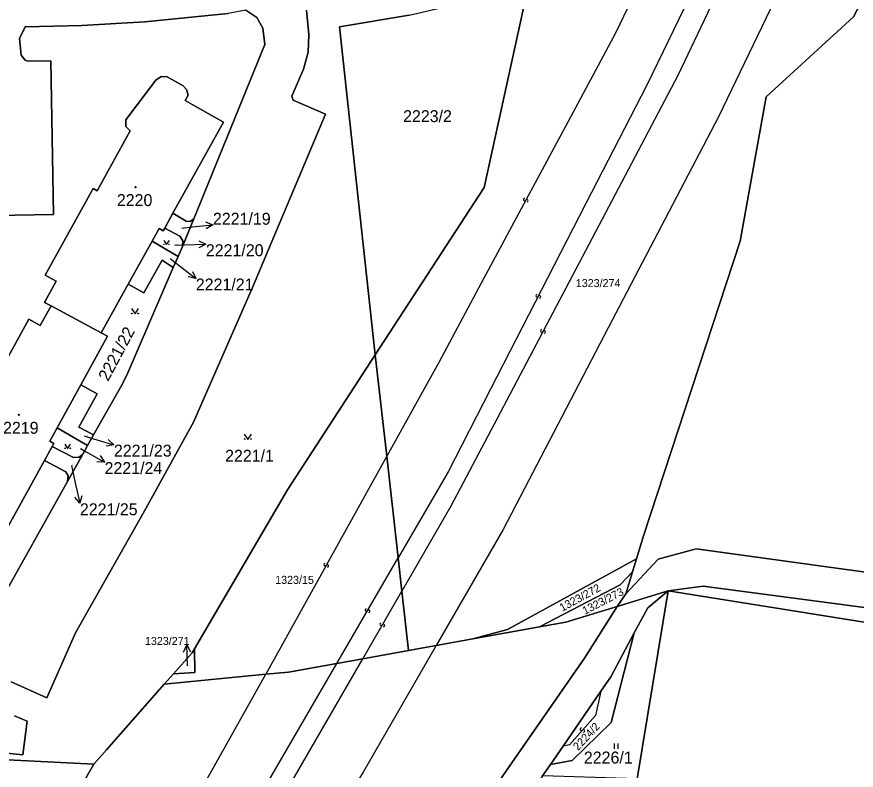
# Model space of a CAD drawing. Extents: x -596024 to -594475, y -1163820 to -1161957.
# Drawn here: x -595718.4 to -595598.9, y -1162998.7 to -1162891.5 of the extents above; entities that cross this region are included whole.
import ezdxf

# ---------------------------------------------------------------- set-up
doc = ezdxf.new("R2010")
doc.units = 0
for name, color, linetype in [('Level 1', 7, 'Continuous'), ('Level 13', 7, 'Continuous'), ('Level 3', 7, 'Continuous'), ('Level 4', 7, 'Continuous'), ('Level 5', 7, 'Continuous'), ('Level 57', 7, 'Continuous'), ('Level 60', 7, 'Continuous')]:
    doc.layers.add(name, color=color, linetype=linetype)

msp = doc.modelspace()

# ---------------------------------------------------------------- linework, layer by layer
at = {"layer": 'Level 1'}
for points in [[(-595630.19, -1162968.62), (-595629.19, -1162965.35), (-595615.44, -1162923.38), (-595611.72, -1162902.85), (-595599.31, -1162891.47), (-595588.22, -1162870.34)], [(-595667.38, -1162939.58), (-595672.49, -1162892.86), (-595662.54, -1162891.24), (-595655.79, -1162889.65), (-595645.71, -1162887.95)], [(-595645.71, -1162887.95), (-595645.96, -1162888.65), (-595651.89, -1162915.77), (-595667.38, -1162939.58)], [(-595693.22, -1162920.24), (-595683.12, -1162895.39), (-595683.38, -1162893.05), (-595684.22, -1162891.57), (-595685.82, -1162890.52), (-595688.3, -1162890.99), (-595700.2, -1162892.18), (-595709.16, -1162892.71), (-595717.23, -1162892.88), (-595718.04, -1162894.54), (-595717.8, -1162896.93), (-595717.22, -1162897.62), (-595716.82, -1162897.78), (-595713.57, -1162897.71), (-595713.19, -1162919.59), (-595726.95, -1162919.86), (-595727.33, -1162903.91), (-595724.32, -1162903.81), (-595723.24, -1162903.33), (-595722.76, -1162902.31), (-595722.85, -1162899.32)], [(-595677.17, -1162890.52), (-595676.82, -1162893.99), (-595676.91, -1162896.47), (-595677.6, -1162898.92), (-595679.26, -1162902.77), (-595679.06, -1162903.34), (-595674.47, -1162905.32), (-595684.86, -1162930.01), (-595693.24, -1162949.18), (-595700.3, -1162961.9), (-595710.04, -1162979.15), (-595714.14, -1162988.41), (-595719.22, -1162986.15)], [(-595696.19, -1162919.43), (-595688.99, -1162906.45), (-595694.45, -1162903.39), (-595694.01, -1162902.63), (-595694.23, -1162901.79), (-595694.71, -1162901.26), (-595697.01, -1162899.98), (-595697.86, -1162899.95), (-595698.6, -1162900.47), (-595702.88, -1162906.13), (-595702.91, -1162907.06), (-595702.25, -1162907.7), (-595706.97, -1162916.22), (-595707.56, -1162915.9), (-595714.36, -1162928.22), (-595712.81, -1162929.09), (-595714.49, -1162932.12), (-595713.54, -1162932.62)], [(-595696.19, -1162919.43), (-595697.35, -1162921.53)], [(-595693.22, -1162920.24), (-595693.73, -1162920.62), (-595694.3, -1162920.55), (-595696.19, -1162919.43)], [(-595694.82, -1162924.14), (-595693.22, -1162920.24)], [(-595697.35, -1162921.53), (-595697.57, -1162921.93), (-595698.16, -1162921.6), (-595699.15, -1162923.39)], [(-595697.35, -1162921.53), (-595695.22, -1162922.69), (-595694.76, -1162923.34), (-595694.82, -1162924.14)], [(-595699.15, -1162923.39), (-595702.54, -1162929.51)], [(-595699.15, -1162923.39), (-595695.45, -1162925.59)], [(-595695.45, -1162925.59), (-595694.82, -1162924.14)], [(-595702.54, -1162929.51), (-595700.31, -1162930.75), (-595697.74, -1162926.11), (-595696.14, -1162927.15)], [(-595696.14, -1162927.15), (-595695.45, -1162925.59)], [(-595707.48, -1162951), (-595703.61, -1162944.16), (-595702.77, -1162942.46), (-595696.14, -1162927.15)], [(-595702.54, -1162929.51), (-595706.38, -1162936.44)], [(-595714.48, -1162954.64), (-595721.66, -1162967.63), (-595727.51, -1162964.42), (-595727.84, -1162965.02), (-595728.39, -1162965.52), (-595729.16, -1162965.5), (-595731.52, -1162964.15), (-595732.1, -1162963.32), (-595732.02, -1162962.36), (-595729.25, -1162956.09), (-595728.72, -1162955.58), (-595727.97, -1162955.63), (-595727.68, -1162955.8), (-595722.91, -1162947.21), (-595723.53, -1162946.88), (-595716.68, -1162934.52), (-595715.1, -1162935.42), (-595713.54, -1162932.62)], [(-595713.54, -1162932.62), (-595706.38, -1162936.44)], [(-595709.29, -1162943.85), (-595705.48, -1162936.94), (-595706.38, -1162936.44)], [(-595667.38, -1162939.58), (-595679.87, -1162958.79), (-595693.12, -1162981.45)], [(-595667.38, -1162939.58), (-595665.75, -1162954.03)], [(-595709.29, -1162943.85), (-595712.68, -1162949.98)], [(-595707.48, -1162951), (-595709.6, -1162949.89), (-595706.97, -1162945.13), (-595709.29, -1162943.85)], [(-595712.68, -1162949.98), (-595713.72, -1162951.86), (-595713.12, -1162952.19), (-595713.36, -1162952.62)], [(-595708.33, -1162952.49), (-595712.68, -1162949.98)], [(-595708.33, -1162952.49), (-595707.48, -1162951)], [(-595709.02, -1162953.74), (-595708.33, -1162952.49)], [(-595713.36, -1162952.62), (-595714.48, -1162954.64)], [(-595713.36, -1162952.62), (-595710.35, -1162954.19), (-595709.54, -1162954.17), (-595709.02, -1162953.74)], [(-595711.21, -1162957.6), (-595711.09, -1162956.83), (-595711.41, -1162956.25), (-595714.48, -1162954.64)], [(-595709.02, -1162953.74), (-595711.21, -1162957.6)], [(-595665.75, -1162954.03), (-595664.12, -1162968.5)], [(-595745.94, -1162977.39), (-595743.24, -1162978.4), (-595735.08, -1162983.24), (-595732.84, -1162984.27), (-595731.36, -1162984.28), (-595729.42, -1162983.44), (-595726.53, -1162980.93), (-595727.15, -1162979.82), (-595728.41, -1162978.62), (-595730.66, -1162982.6), (-595742.82, -1162975.76), (-595740.35, -1162971.64), (-595737.88, -1162967.26), (-595729.97, -1162971.67), (-595727.71, -1162967.77), (-595723.54, -1162970.18), (-595725.76, -1162974.06), (-595724.16, -1162974.93), (-595722.52, -1162975.26), (-595721.06, -1162975.18), (-595711.21, -1162957.6)], [(-595631.72, -1162973.61), (-595627.1, -1162968.66), (-595621.68, -1162967.22), (-595580.37, -1162972.91), (-595548.72, -1162976.84), (-595533.58, -1162977.77), (-595526.44, -1162978.13), (-595523.36, -1162976.45), (-595521.48, -1162971.75)], [(-595664.12, -1162968.5), (-595663.59, -1162973.22)], [(-595653.47, -1162980.02), (-595648.57, -1162978.69), (-595630.19, -1162968.62)], [(-595630.76, -1162970.47), (-595630.19, -1162968.62)], [(-595644.02, -1162978.31), (-595632.51, -1162972.36), (-595630.76, -1162970.47)], [(-595631.72, -1162973.61), (-595630.76, -1162970.47)], [(-595625.67, -1162973.19), (-595620.68, -1162972.51), (-595581.97, -1162977.67), (-595549.49, -1162981.93), (-595533.77, -1162984.14), (-595525.67, -1162985.49), (-595519.93, -1162988.52)], [(-595663.59, -1162973.22), (-595662.64, -1162981.68)], [(-595625.67, -1162973.19), (-595632.94, -1162975.42)], [(-595632.94, -1162975.42), (-595631.72, -1162973.61)], [(-595630.51, -1162979.19), (-595628.58, -1162975.6), (-595625.67, -1162973.19)], [(-595625.67, -1162973.19), (-595630.09, -1162999.96)], [(-595519.69, -1162990.12), (-595625.67, -1162973.19)], [(-595703.87, -1163071.37), (-595698.09, -1163065.01), (-595678.51, -1163041.57), (-595661.53, -1163017.48), (-595648.68, -1162998.76), (-595637.58, -1162982.79), (-595632.94, -1162975.42)], [(-595632.94, -1162975.42), (-595640.24, -1162977.63), (-595644.02, -1162978.31)], [(-595644.02, -1162978.31), (-595653.47, -1162980.02)], [(-595630.51, -1162979.19), (-595633.77, -1162991.96), (-595639.33, -1162997.36), (-595642.45, -1162997.93)], [(-595635.27, -1162987.48), (-595633.85, -1162985.42), (-595630.51, -1162979.19)], [(-595658.71, -1162980.97), (-595662.64, -1162981.68)], [(-595653.47, -1162980.02), (-595658.71, -1162980.97)], [(-595696.12, -1162985), (-595693.45, -1162982.01), (-595693.12, -1162981.45)], [(-595696.12, -1162985), (-595693.09, -1162984.81), (-595693.12, -1162981.45)], [(-595662.64, -1162981.68), (-595669.16, -1162982.86)], [(-595682.97, -1162985.08), (-595679.73, -1162984.77), (-595672.85, -1162983.53)], [(-595669.16, -1162982.86), (-595672.85, -1162983.53)], [(-595696.12, -1162985), (-595697.43, -1162986.48)], [(-595682.97, -1162985.08), (-595697.43, -1162986.48)], [(-595697.43, -1162986.48), (-595703.26, -1162993.12), (-595705.64, -1162995.83), (-595707.44, -1162997.87)], [(-595640.64, -1162995.3), (-595635.27, -1162987.48)], [(-595718.76, -1162990.98), (-595716.93, -1162991.75), (-595717.54, -1162996.55), (-595723.49, -1162995.94)], [(-595642.45, -1162997.93), (-595640.64, -1162995.3)], [(-595746.22, -1162995.91), (-595707.44, -1162997.87)], [(-595707.44, -1162997.87), (-595718.62, -1163017.24)], [(-595643.56, -1162999.54), (-595642.45, -1162997.93)]]:
    msp.add_lwpolyline(points, dxfattribs=at)
at = {"layer": 'Level 13'}
for centre, start, end in [((-595646.11, -1162917.47), 98.9414, 331.5314), ((-595645.79, -1162917.65), 279.1558, 151.2538), ((-595644.33, -1162931.18), 99.9549, 332.5449), ((-595644.01, -1162931.35), 280.1694, 152.2674), ((-595643.66, -1162936.16), 99.3651, 331.9551), ((-595643.34, -1162936.34), 279.5796, 151.6776), ((-595674.52, -1162969.47), 98.146, 330.736), ((-595674.2, -1162969.65), 278.3605, 150.4584), ((-595668.64, -1162975.93), 97.2231, 329.3211), ((-595668.32, -1162976.11), 277.0086, 149.5986), ((-595666.54, -1162977.95), 97.3534, 329.4514), ((-595666.22, -1162978.13), 277.1389, 149.7289), ((-595638.02, -1162992.9), 85.4308, 318.0208), ((-595637.74, -1162993.14), 265.6453, 137.7433)]:
    msp.add_arc(centre, 0.184, start, end, dxfattribs=at)
at = {"layer": 'Level 3'}
for points in [[(-595603.73, -1162874.99), (-595618.53, -1162905.68), (-595634.2, -1162935.72), (-595649.19, -1162964.46), (-595652.89, -1162970.88), (-595658.71, -1162980.97)], [(-595614.02, -1162878.11), (-595624.29, -1162899.81), (-595636.5, -1162922.96), (-595650.51, -1162949.54), (-595656.61, -1162961.12), (-595663.59, -1162973.22)], [(-595618.13, -1162879.3), (-595628.71, -1162901.18), (-595637.38, -1162918.05), (-595650.96, -1162944.47), (-595657.02, -1162956.27), (-595664.12, -1162968.5)], [(-595627.61, -1162882.17), (-595633.14, -1162893.7), (-595639.6, -1162905.74), (-595652.29, -1162929.39), (-595658.34, -1162940.67), (-595665.75, -1162954.03)], [(-595665.75, -1162954.03), (-595682.97, -1162985.08)], [(-595672.85, -1162983.53), (-595664.12, -1162968.5)], [(-595669.16, -1162982.86), (-595663.59, -1162973.22)], [(-595658.71, -1162980.97), (-595669.11, -1162999.02), (-595691.04, -1163034.53), (-595716.06, -1163070.56)], [(-595728.81, -1163069.72), (-595688.36, -1163010.24), (-595672.85, -1162983.53)], [(-595725.06, -1163069.97), (-595689.64, -1163018.35), (-595669.16, -1162982.86)], [(-595738.74, -1163069.07), (-595718.73, -1163041.4), (-595695.75, -1163007.92), (-595682.97, -1162985.08)], [(-595635.27, -1162987.48), (-595636.03, -1162990.94), (-595639.74, -1162995.1), (-595640.64, -1162995.3)]]:
    msp.add_lwpolyline(points, dxfattribs=at)
at = {"layer": 'Level 5'}
for p, q in [((-595633.3, -1162995.7), (-595633.3, -1162994.94)), ((-595632.8, -1162995.7), (-595632.8, -1162994.94))]:
    msp.add_line(p, q, dxfattribs=at)
for points in [[(-595697.49, -1162923.29), (-595697.09, -1162923.89), (-595696.69, -1162923.29)], [(-595702.08, -1162932.99), (-595701.58, -1162933.74), (-595701.08, -1162932.99)], [(-595686.02, -1162950.88), (-595685.52, -1162951.63), (-595685.02, -1162950.88)], [(-595711.58, -1162952.33), (-595711.18, -1162952.93), (-595710.78, -1162952.33)]]:
    msp.add_lwpolyline(points, dxfattribs=at)
for centre, radius in [((-595701.52, -1162915.7), 0.09), ((-595701.52, -1162915.7), 0.0521), ((-595697.45, -1162923.85), 0.04), ((-595696.73, -1162923.85), 0.04), ((-595702.03, -1162933.69), 0.05), ((-595701.13, -1162933.69), 0.05), ((-595718.12, -1162948.13), 0.09), ((-595718.12, -1162948.13), 0.0521), ((-595685.97, -1162951.58), 0.05), ((-595685.07, -1162951.58), 0.05), ((-595711.54, -1162952.89), 0.04), ((-595710.82, -1162952.89), 0.04)]:
    msp.add_circle(centre, radius, dxfattribs=at)
at = {"layer": 'Level 57'}
for p, q in [((-595694.94, -1162921.53), (-595693.47, -1162921.38)), ((-595693.47, -1162921.38), (-595690.49, -1162921.06)), ((-595695.93, -1162923.97), (-595694.5, -1162923.93)), ((-595694.5, -1162923.93), (-595691.5, -1162923.84)), ((-595696.55, -1162925.9), (-595695.3, -1162926.88)), ((-595695.3, -1162926.88), (-595692.93, -1162928.72)), ((-595708.83, -1162951.14), (-595707.47, -1162951.54)), ((-595707.47, -1162951.54), (-595704.59, -1162952.38)), ((-595709.34, -1162952.94), (-595708.54, -1162953.39)), ((-595708.54, -1162953.39), (-595705.92, -1162954.86)), ((-595710.62, -1162955.33), (-595710.08, -1162957.8)), ((-595710.08, -1162957.8), (-595709.43, -1162960.73)), ((-595694.1, -1162983.89), (-595694.19, -1162980.9))]:
    msp.add_line(p, q, dxfattribs=at)
for points in [[(-595691.54, -1162920.67), (-595690.49, -1162921.06), (-595691.43, -1162921.66)], [(-595692.52, -1162923.37), (-595691.5, -1162923.84), (-595692.48, -1162924.37)], [(-595693.41, -1162927.71), (-595692.93, -1162928.72), (-595694.03, -1162928.5)], [(-595705.41, -1162951.62), (-595704.59, -1162952.38), (-595705.69, -1162952.58)], [(-595706.55, -1162953.93), (-595705.92, -1162954.86), (-595707.04, -1162954.81)], [(-595709.16, -1162959.65), (-595709.43, -1162960.73), (-595710.13, -1162959.86)], [(-595694.66, -1162981.91), (-595694.19, -1162980.9), (-595693.66, -1162981.88)]]:
    msp.add_lwpolyline(points, dxfattribs=at)
at = {"layer": 'Level 60'}
for points in [[(-595533.58, -1162977.77), (-595548.72, -1162976.84), (-595580.37, -1162972.91), (-595621.68, -1162967.22), (-595627.1, -1162968.66), (-595631.72, -1162973.61), (-595630.76, -1162970.47), (-595630.19, -1162968.62), (-595629.19, -1162965.35), (-595615.44, -1162923.38), (-595611.72, -1162902.85), (-595599.31, -1162891.47), (-595588.22, -1162870.34), (-595577.24, -1162866.72), (-595550.23, -1162857.95), (-595540.49, -1162858.64), (-595532.01, -1162864.98), (-595527.95, -1162892.49), (-595526.75, -1162917.62), (-595523.56, -1162952.96), (-595522.19, -1162968.12), (-595521.48, -1162971.75), (-595523.36, -1162976.45), (-595526.44, -1162978.13)], [(-595645.96, -1162888.65), (-595651.89, -1162915.77), (-595667.38, -1162939.58), (-595672.49, -1162892.86), (-595662.54, -1162891.24), (-595655.79, -1162889.65), (-595645.71, -1162887.95)], [(-595706.38, -1162936.44), (-595713.54, -1162932.62), (-595714.49, -1162932.12), (-595712.81, -1162929.09), (-595714.36, -1162928.22), (-595707.56, -1162915.9), (-595706.97, -1162916.22), (-595702.25, -1162907.7), (-595702.91, -1162907.06), (-595702.88, -1162906.13), (-595698.6, -1162900.47), (-595697.86, -1162899.95), (-595697.01, -1162899.98), (-595694.71, -1162901.26), (-595694.23, -1162901.79), (-595694.01, -1162902.63), (-595694.45, -1162903.39), (-595688.99, -1162906.45), (-595696.19, -1162919.43), (-595697.35, -1162921.53), (-595697.57, -1162921.93), (-595698.16, -1162921.6), (-595699.15, -1162923.39), (-595702.54, -1162929.51)], [(-595693.22, -1162920.24), (-595694.82, -1162924.14), (-595694.76, -1162923.34), (-595695.22, -1162922.69), (-595697.35, -1162921.53), (-595696.19, -1162919.43), (-595694.3, -1162920.55), (-595693.73, -1162920.62)], [(-595694.82, -1162924.14), (-595695.45, -1162925.59), (-595699.15, -1162923.39), (-595698.16, -1162921.6), (-595697.57, -1162921.93), (-595697.35, -1162921.53), (-595695.22, -1162922.69), (-595694.76, -1162923.34)], [(-595695.45, -1162925.59), (-595696.14, -1162927.15), (-595697.74, -1162926.11), (-595700.31, -1162930.75), (-595702.54, -1162929.51), (-595699.15, -1162923.39)], [(-595696.14, -1162927.15), (-595702.77, -1162942.46), (-595703.61, -1162944.16), (-595707.48, -1162951), (-595709.6, -1162949.89), (-595706.97, -1162945.13), (-595709.29, -1162943.85), (-595705.48, -1162936.94), (-595706.38, -1162936.44), (-595702.54, -1162929.51), (-595700.31, -1162930.75), (-595697.74, -1162926.11)], [(-595679.87, -1162958.79), (-595667.38, -1162939.58), (-595665.75, -1162954.03), (-595664.12, -1162968.5), (-595663.59, -1162973.22), (-595662.64, -1162981.68), (-595669.16, -1162982.86), (-595672.85, -1162983.53), (-595679.73, -1162984.77), (-595682.97, -1162985.08), (-595697.43, -1162986.48), (-595696.12, -1162985), (-595693.09, -1162984.81), (-595693.12, -1162981.45)], [(-595707.48, -1162951), (-595708.33, -1162952.49), (-595712.68, -1162949.98), (-595709.29, -1162943.85), (-595706.97, -1162945.13), (-595709.6, -1162949.89)], [(-595708.33, -1162952.49), (-595709.02, -1162953.74), (-595709.54, -1162954.17), (-595710.35, -1162954.19), (-595713.36, -1162952.62), (-595713.12, -1162952.19), (-595713.72, -1162951.86), (-595712.68, -1162949.98)], [(-595709.02, -1162953.74), (-595711.21, -1162957.6), (-595711.09, -1162956.83), (-595711.41, -1162956.25), (-595714.48, -1162954.64), (-595713.36, -1162952.62), (-595710.35, -1162954.19), (-595709.54, -1162954.17)], [(-595632.94, -1162975.42), (-595631.72, -1162973.61), (-595627.1, -1162968.66), (-595621.68, -1162967.22), (-595580.37, -1162972.91), (-595548.72, -1162976.84), (-595533.58, -1162977.77), (-595526.44, -1162978.13), (-595523.36, -1162976.45), (-595521.48, -1162971.75), (-595520.8, -1162972.23), (-595515.96, -1162992.22), (-595519.93, -1162988.52), (-595525.67, -1162985.49), (-595533.77, -1162984.14), (-595549.49, -1162981.93), (-595581.97, -1162977.67), (-595620.68, -1162972.51), (-595625.67, -1162973.19)], [(-595644.02, -1162978.31), (-595653.47, -1162980.02), (-595648.57, -1162978.69), (-595630.19, -1162968.62), (-595630.76, -1162970.47), (-595632.51, -1162972.36)], [(-595631.72, -1162973.61), (-595632.94, -1162975.42), (-595640.24, -1162977.63), (-595644.02, -1162978.31), (-595632.51, -1162972.36), (-595630.76, -1162970.47)], [(-595549.49, -1162981.93), (-595533.77, -1162984.14), (-595525.67, -1162985.49), (-595519.93, -1162988.52), (-595519.69, -1162990.12), (-595625.67, -1162973.19), (-595620.68, -1162972.51), (-595581.97, -1162977.67)], [(-595642.03, -1162999.6), (-595643.56, -1162999.54), (-595642.45, -1162997.93), (-595639.33, -1162997.36), (-595633.77, -1162991.96), (-595630.51, -1162979.19), (-595628.58, -1162975.6), (-595625.67, -1162973.19), (-595630.09, -1162999.96)], [(-595636.96, -1163041.67), (-595636.94, -1163041.47), (-595633.71, -1163021.93), (-595630.09, -1162999.96), (-595625.67, -1162973.19), (-595519.69, -1162990.12), (-595520.77, -1162996.86), (-595530.65, -1163058.63), (-595530.95, -1163058.58), (-595542.17, -1163056.79), (-595553.89, -1163054.92), (-595577.37, -1163051.18), (-595614.28, -1163045.29)], [(-595642.45, -1162997.93), (-595640.64, -1162995.3), (-595635.27, -1162987.48), (-595633.85, -1162985.42), (-595630.51, -1162979.19), (-595633.77, -1162991.96), (-595639.33, -1162997.36)], [(-595696.12, -1162985), (-595693.45, -1162982.01), (-595693.12, -1162981.45), (-595693.09, -1162984.81)], [(-595746.55, -1163016.16), (-595746.22, -1162995.91), (-595707.44, -1162997.87), (-595718.62, -1163017.24)]]:
    msp.add_lwpolyline(points, close=True, dxfattribs=at)
for points in [[(-595588.22, -1162870.34), (-595599.31, -1162891.47), (-595611.72, -1162902.85), (-595615.44, -1162923.38), (-595629.19, -1162965.35), (-595630.19, -1162968.62), (-595648.57, -1162978.69), (-595653.47, -1162980.02), (-595658.71, -1162980.97), (-595662.64, -1162981.68), (-595663.59, -1162973.22), (-595664.12, -1162968.5), (-595665.75, -1162954.03), (-595667.38, -1162939.58), (-595651.89, -1162915.77), (-595645.96, -1162888.65)], [(-595662.54, -1162891.24), (-595672.49, -1162892.86), (-595667.38, -1162939.58), (-595679.87, -1162958.79), (-595693.12, -1162981.45), (-595693.45, -1162982.01), (-595696.12, -1162985), (-595697.43, -1162986.48), (-595703.26, -1162993.12), (-595705.64, -1162995.83), (-595707.44, -1162997.87), (-595746.22, -1162995.91)], [(-595688.3, -1162890.99), (-595700.2, -1162892.18), (-595709.16, -1162892.71), (-595717.23, -1162892.88), (-595718.04, -1162894.54), (-595717.8, -1162896.93), (-595717.22, -1162897.62), (-595716.82, -1162897.78), (-595713.57, -1162897.71), (-595713.19, -1162919.59), (-595726.95, -1162919.86)], [(-595685.82, -1162890.52), (-595684.22, -1162891.57), (-595683.38, -1162893.05), (-595683.12, -1162895.39), (-595693.22, -1162920.24), (-595693.73, -1162920.62), (-595694.3, -1162920.55), (-595696.19, -1162919.43), (-595688.99, -1162906.45), (-595694.45, -1162903.39), (-595694.01, -1162902.63), (-595694.23, -1162901.79), (-595694.71, -1162901.26), (-595697.01, -1162899.98), (-595697.86, -1162899.95), (-595698.6, -1162900.47), (-595702.88, -1162906.13), (-595702.91, -1162907.06), (-595702.25, -1162907.7), (-595706.97, -1162916.22), (-595707.56, -1162915.9), (-595714.36, -1162928.22), (-595712.81, -1162929.09), (-595714.49, -1162932.12), (-595713.54, -1162932.62), (-595715.1, -1162935.42), (-595716.68, -1162934.52), (-595723.53, -1162946.88)], [(-595721.06, -1162975.18), (-595711.21, -1162957.6), (-595709.02, -1162953.74), (-595708.33, -1162952.49), (-595707.48, -1162951), (-595703.61, -1162944.16), (-595702.77, -1162942.46), (-595696.14, -1162927.15), (-595695.45, -1162925.59), (-595694.82, -1162924.14), (-595693.22, -1162920.24), (-595683.12, -1162895.39), (-595683.38, -1162893.05), (-595684.22, -1162891.57), (-595685.82, -1162890.52)], [(-595719.22, -1162986.15), (-595714.14, -1162988.41), (-595710.04, -1162979.15), (-595700.3, -1162961.9), (-595693.24, -1162949.18), (-595684.86, -1162930.01), (-595674.47, -1162905.32), (-595679.06, -1162903.34), (-595679.26, -1162902.77), (-595677.6, -1162898.92), (-595676.91, -1162896.47), (-595676.82, -1162893.99), (-595677.17, -1162890.52)], [(-595677.17, -1162890.52), (-595676.82, -1162893.99), (-595676.91, -1162896.47), (-595677.6, -1162898.92), (-595679.26, -1162902.77), (-595679.06, -1162903.34), (-595674.47, -1162905.32), (-595684.86, -1162930.01), (-595693.24, -1162949.18), (-595700.3, -1162961.9), (-595710.04, -1162979.15), (-595714.14, -1162988.41), (-595719.22, -1162986.15)], [(-595717.8, -1162896.93), (-595718.04, -1162894.54), (-595717.23, -1162892.88), (-595709.16, -1162892.71), (-595700.2, -1162892.18), (-595688.3, -1162890.99)], [(-595726.95, -1162919.86), (-595713.19, -1162919.59), (-595713.57, -1162897.71), (-595716.82, -1162897.78), (-595717.22, -1162897.62), (-595717.8, -1162896.93)], [(-595723.53, -1162946.88), (-595716.68, -1162934.52), (-595715.1, -1162935.42), (-595713.54, -1162932.62), (-595706.38, -1162936.44), (-595705.48, -1162936.94), (-595709.29, -1162943.85), (-595712.68, -1162949.98), (-595713.72, -1162951.86), (-595713.12, -1162952.19), (-595713.36, -1162952.62), (-595714.48, -1162954.64), (-595721.66, -1162967.63)], [(-595721.66, -1162967.63), (-595714.48, -1162954.64), (-595711.41, -1162956.25), (-595711.09, -1162956.83), (-595711.21, -1162957.6), (-595721.06, -1162975.18)], [(-595698.09, -1163065.01), (-595678.51, -1163041.57), (-595661.53, -1163017.48), (-595648.68, -1162998.76), (-595637.58, -1162982.79), (-595632.94, -1162975.42), (-595625.67, -1162973.19), (-595628.58, -1162975.6), (-595630.51, -1162979.19), (-595633.85, -1162985.42), (-595635.27, -1162987.48), (-595640.64, -1162995.3), (-595642.45, -1162997.93), (-595643.56, -1162999.54), (-595655.99, -1163017.63), (-595657.25, -1163019.45), (-595657.45, -1163019.75), (-595658.64, -1163021.44), (-595666.72, -1163032.91), (-595674.26, -1163043.61), (-595674.71, -1163044.25), (-595689.34, -1163060.83), (-595690.94, -1163062.64), (-595695.02, -1163067.26)], [(-595718.62, -1163017.24), (-595707.44, -1162997.87), (-595705.64, -1162995.83), (-595703.26, -1162993.12), (-595697.43, -1162986.48), (-595682.97, -1162985.08), (-595679.73, -1162984.77), (-595672.85, -1162983.53), (-595669.16, -1162982.86), (-595662.64, -1162981.68), (-595658.71, -1162980.97), (-595653.47, -1162980.02), (-595644.02, -1162978.31), (-595640.24, -1162977.63), (-595632.94, -1162975.42), (-595637.58, -1162982.79), (-595648.68, -1162998.76), (-595661.53, -1163017.48), (-595678.51, -1163041.57), (-595698.09, -1163065.01)], [(-595723.49, -1162995.94), (-595717.54, -1162996.55), (-595716.93, -1162991.75), (-595718.76, -1162990.98)], [(-595718.76, -1162990.98), (-595716.93, -1162991.75), (-595717.54, -1162996.55), (-595723.49, -1162995.94)]]:
    msp.add_lwpolyline(points, dxfattribs=at)

# ---------------------------------------------------------------- texts
at = {"layer": 'Level 4'}
for s, height, p in [('2223/2', 1.7, (-595663.42, -1162906.45)), ('2220', 1.7, (-595704.17, -1162918.4)), ('2221/19', 0.1, (-595694.94, -1162921.53)), ('2221/20', 0.1, (-595695.93, -1162923.97)), ('2221/21', 0.1, (-595696.55, -1162925.9)), ('1323/274', 1.14, (-595638.83, -1162929.94)), ('2219', 1.7, (-595720.37, -1162950.83)), ('2221/23', 0.1, (-595708.83, -1162951.14)), ('2221/24', 0.1, (-595709.34, -1162952.94)), ('2221/1', 1.7, (-595688.76, -1162954.81)), ('2221/25', 0.1, (-595710.62, -1162955.33)), ('1323/15', 1.14, (-595681.63, -1162972.2)), ('1323/271', 0.1, (-595694.1, -1162983.89)), ('2226/1', 1.7, (-595637.68, -1162997.78))]:
    msp.add_text(s, height=height, dxfattribs=at).set_placement(p)
for s, height, rotation, p in [('2221/22', 1.7, 61.9, (-595705.41, -1162943.45)), ('1323/272', 1.14, 28.7131, (-595640.76, -1162976.18)), ('1323/273', 1.14, 27.3363, (-595637.53, -1162976.61)), ('2224/2', 1.14, 46.7123, (-595638.51, -1162996.01))]:
    msp.add_text(s, height=height, rotation=rotation, dxfattribs=at).set_placement(p)
at = {"layer": 'Level 57'}
for s, height, p in [('2221/19', 1.7, (-595690.49, -1162921.06)), ('2221/20', 1.7, (-595691.5, -1162925.54)), ('2221/21', 1.7, (-595692.93, -1162930.42)), ('2221/23', 1.7, (-595704.59, -1162954.08)), ('2221/24', 1.7, (-595705.92, -1162956.56)), ('2221/25', 1.7, (-595709.43, -1162962.43)), ('1323/271', 1.14, (-595700.17, -1162980.9))]:
    msp.add_text(s, height=height, dxfattribs=at).set_placement(p)

doc.saveas('drawing.dxf')
